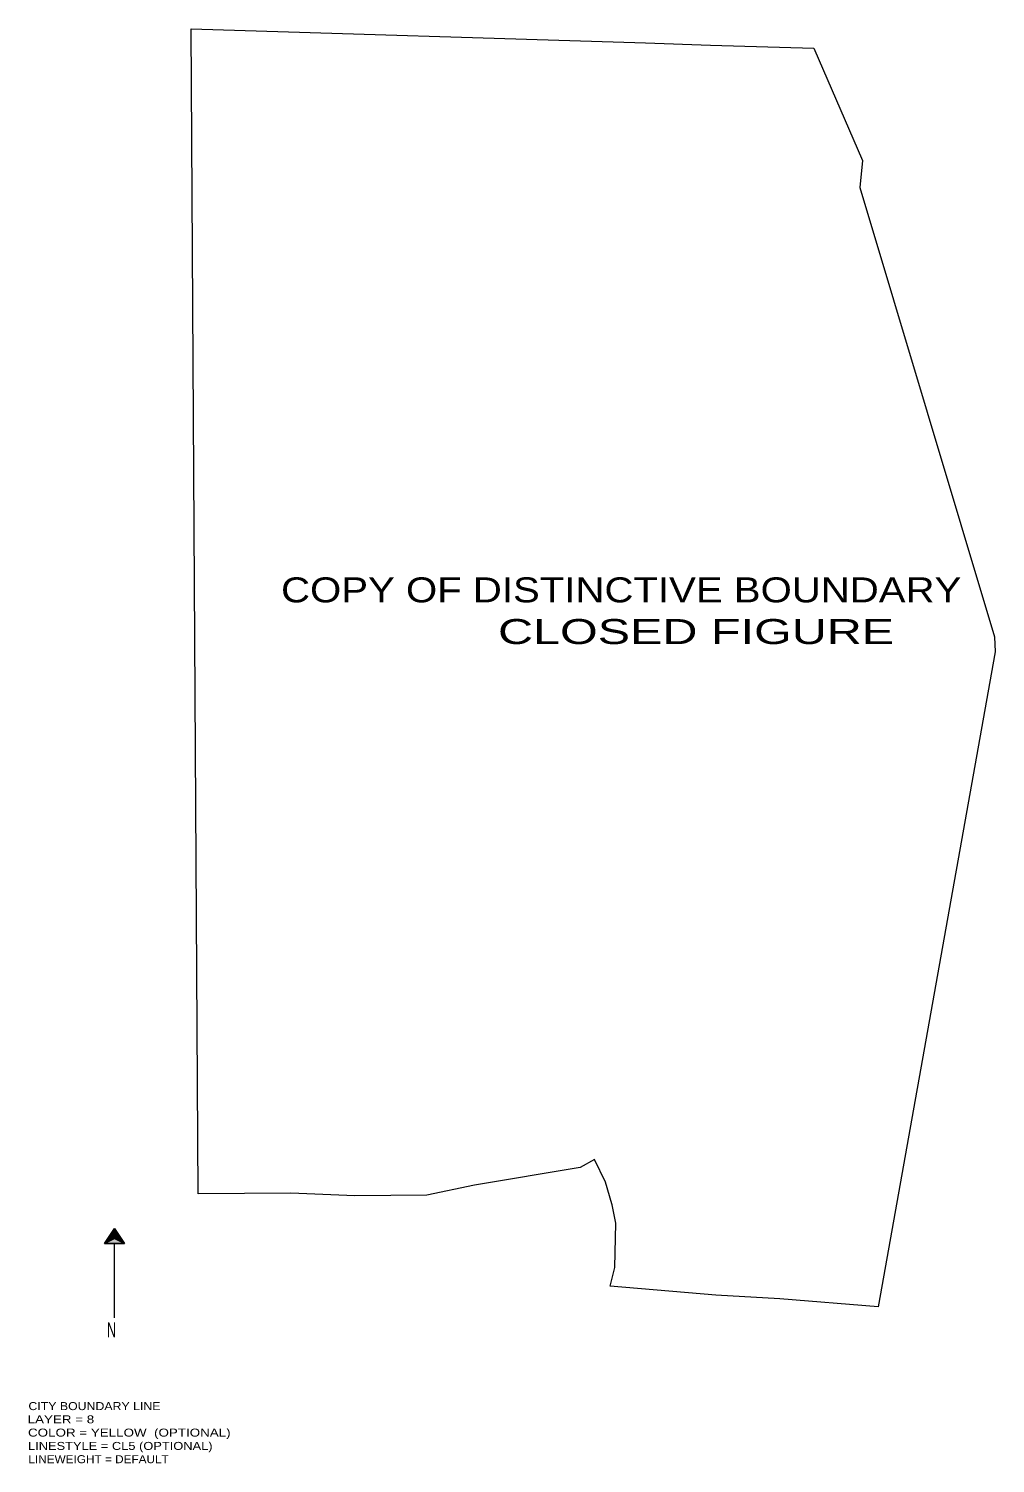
# Model space of a CAD drawing. Extents: x 6387474 to 6390971, y 1972046 to 1973920.
# Drawn here: x 6390005 to 6390971, y 1972119 to 1973553 of the extents above; entities that cross this region are included whole.
import ezdxf

# ---------------------------------------------------------------- set-up
doc = ezdxf.new("R2010")
doc.units = 0
doc.header["$LTSCALE"] = 4
doc.layers.add('8', color=7, linetype='Continuous', lineweight=13)
doc.layers.add('9', color=7, linetype='Continuous')

msp = doc.modelspace()

# ---------------------------------------------------------------- hatches: boundary and pattern name
at = {"layer": '8'}
for points in [[(6390090.602, 1972343.176), (6390080.602, 1972338.176), (6390090.602, 1972353.176)], [(6390090.602, 1972343.176), (6390090.602, 1972353.176), (6390100.602, 1972338.176)], [(6390090.602, 1972343.176), (6390100.602, 1972338.176), (6390080.602, 1972338.176)]]:
    msp.add_hatch(color=256, dxfattribs=at).paths.add_polyline_path(points)

# ---------------------------------------------------------------- linework, layer by layer
for p, q in [((6390090.602, 1972353.176), (6390100.602, 1972338.176)), ((6390090.602, 1972263.988), (6390090.602, 1972338.176))]:
    msp.add_line(p, q, dxfattribs=at)
for points in [[(6390837.993, 1973420.866), (6390835.25, 1973394.066), (6390969.848, 1972944.722), (6390970.709, 1972929.685), (6390853.801, 1972274.953), (6390755.356, 1972282.98), (6390691.452, 1972286.766), (6390585.738, 1972295.807), (6390590.533, 1972314.388), (6390591.431, 1972358.759), (6390587.82, 1972377.117), (6390587.635, 1972378.059), (6390581.135, 1972399.757), (6390570.122, 1972422.29), (6390555.756, 1972414.358), (6390450.227, 1972396.738), (6390402.692, 1972386.478), (6390330.693, 1972386.043), (6390266.677, 1972388.555), (6390174.178, 1972387.996), (6390167.131, 1973552.734), (6390621.221, 1973538.455), (6390685.933, 1973536.42), (6390789.454, 1973533.165)], [(6390090.602, 1972343.176), (6390080.602, 1972338.176), (6390090.602, 1972353.176)], [(6390090.602, 1972343.176), (6390090.602, 1972353.176), (6390100.602, 1972338.176)], [(6390090.602, 1972343.176), (6390100.602, 1972338.176), (6390080.602, 1972338.176)]]:
    msp.add_lwpolyline(points, close=True, dxfattribs=at)
msp.add_lwpolyline([(6390090.602, 1972353.176), (6390080.602, 1972338.176), (6390100.602, 1972338.176)], dxfattribs=at)

# ---------------------------------------------------------------- texts
for s, height, width, p in [('N', 15, 0.65, (6390082.746, 1972244.479)), ('CITY BOUNDARY LINE', 8, 1.15, (6390004.444, 1972171.769)), ('LAYER = 8', 8, 1.25, (6390003.632, 1972158.521)), ('COLOR = YELLOW  (OPTIONAL)', 8, 1.25, (6390004.024, 1972145.263)), ('LINESTYLE = CL5 (OPTIONAL)', 8, 1.2, (6390004.024, 1972131.943)), ('LINEWEIGHT = DEFAULT', 8, 1.1, (6390004.416, 1972118.685))]:
    msp.add_text(s, height=height, dxfattribs=dict(at, width=width)).set_placement(p)
at = {"layer": '9'}
for s, width, p in [('COPY OF DISTINCTIVE BOUNDARY', 1.2, (6390256.903, 1972979.233)), ('                CLOSED FIGURE', 1.45, (6390258.236, 1972937.566))]:
    msp.add_text(s, height=25, dxfattribs=dict(at, width=width)).set_placement(p)

doc.saveas('drawing.dxf')
